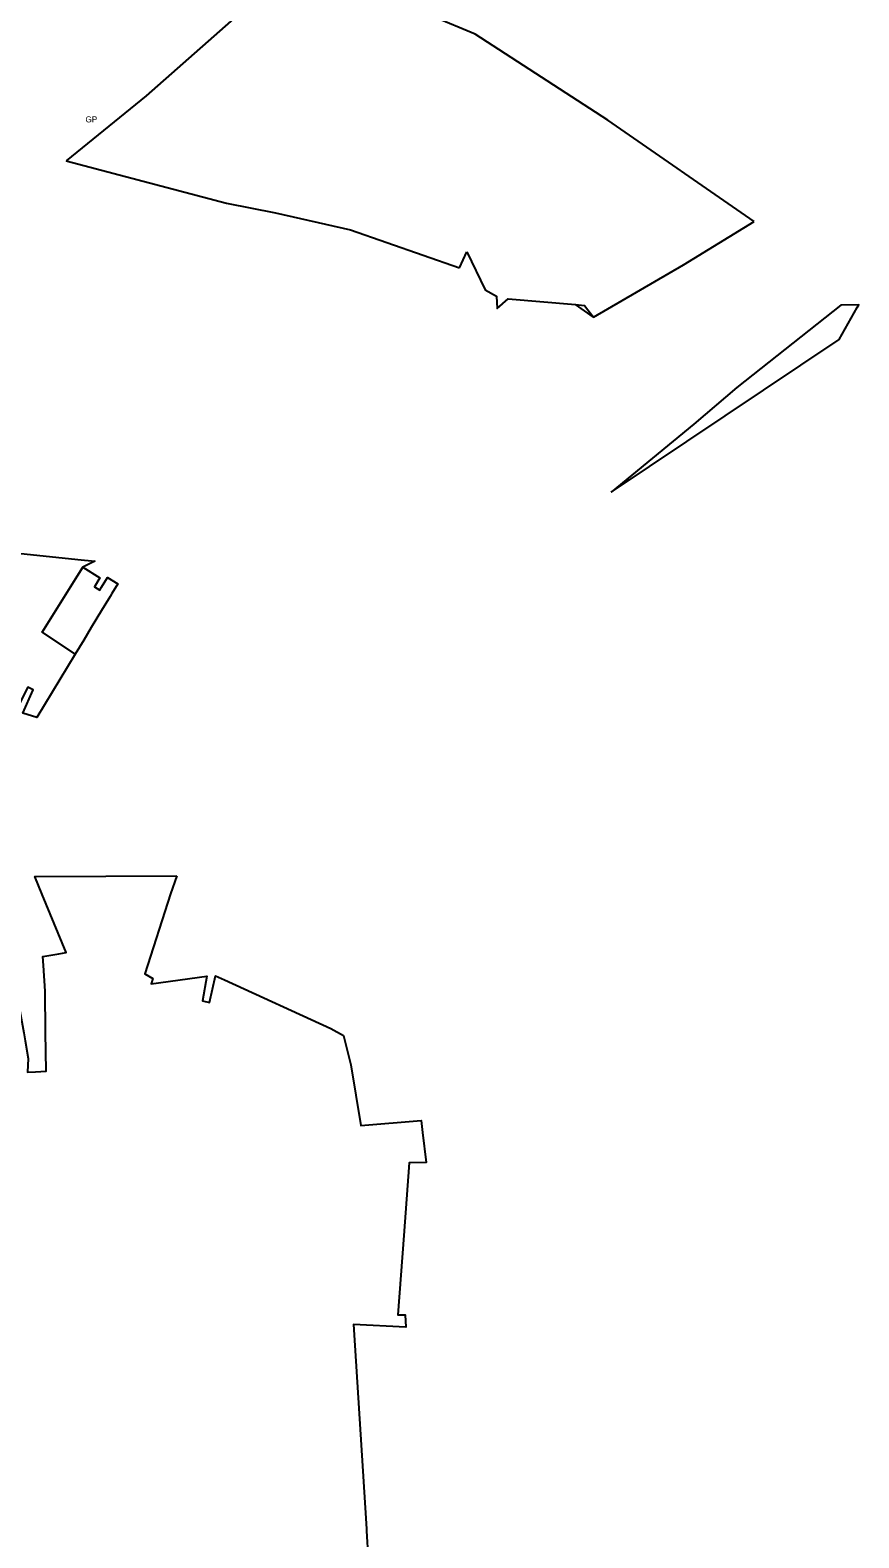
# Model space of a CAD drawing. Extents: x -615719 to -612048, y -1104937 to -1102684.
# Drawn here: x -614082 to -613807.9, y -1103880.3 to -1103382 of the extents above; entities that cross this region are included whole.
import ezdxf

# ---------------------------------------------------------------- set-up
doc = ezdxf.new("R2010")
doc.units = 0
for name, color, linetype in [('GRA_ZV', 7, 'Continuous'), ('OVNI_PRE', 7, 'Continuous'), ('OVNI_SET', 7, 'Continuous'), ('POZN', 7, 'Continuous')]:
    doc.layers.add(name, color=color, linetype=linetype)

msp = doc.modelspace()

# ---------------------------------------------------------------- linework, layer by layer
at = {"layer": 'GRA_ZV'}
for points in [[(-613901.68, -1103472.68), (-613898.69, -1103472.93), (-613895.74, -1103476.88), (-613901.68, -1103472.68)], [(-613889.8, -1103534.71), (-613814.44, -1103484.24), (-613808.46, -1103473.66), (-613807.92, -1103472.71), (-613813.93, -1103472.84), (-613848.23, -1103500.04), (-613862.55, -1103512.21), (-613889.8, -1103534.71)], [(-614086.05, -1103554.8), (-614066.22, -1103556.93), (-614060.57, -1103557.54), (-614064.61, -1103559.48), (-614066.46, -1103562.44), (-614077.99, -1103580.96), (-614067.16, -1103588.26), (-614079.8, -1103609.17), (-614084.44, -1103607.77), (-614081.04, -1103600.03), (-614082.74, -1103599.1), (-614088.16, -1103609.79), (-614091.36, -1103623.82), (-614086.05, -1103554.8)]]:
    msp.add_lwpolyline(points, dxfattribs=at)
at = {"layer": 'OVNI_PRE'}
for points in [[(-614017.12, -1103439.18), (-614000.92, -1103442.32), (-613976.07, -1103447.93), (-613940.05, -1103460.47)], [(-613970.78, -1103877.34), (-613970.75, -1103878.04), (-613970.18, -1103887.33), (-613988.53, -1103889.19)]]:
    msp.add_lwpolyline(points, dxfattribs=at)
at = {"layer": 'OVNI_SET'}
for p, q in [((-614043.63, -1103403.62), (-614070.05, -1103425.19)), ((-613842.51, -1103445.17), (-613891, -1103411.75)), ((-614070.05, -1103425.19), (-614017.12, -1103439.18)), ((-613940.05, -1103460.47), (-613937.63, -1103455.28))]:
    msp.add_line(p, q, dxfattribs=at)
for points in [[(-613934.8, -1103383.27), (-613976.14, -1103365.99), (-613993.27, -1103359.19), (-614043.63, -1103403.62)], [(-613891, -1103411.75), (-613896.93, -1103407.9), (-613934.8, -1103383.27)], [(-613937.63, -1103455.28), (-613931.48, -1103467.77), (-613927.79, -1103469.85), (-613927.6, -1103473.95), (-613923.95, -1103470.8), (-613901.68, -1103472.68), (-613898.69, -1103472.93), (-613895.74, -1103476.88), (-613865.94, -1103459.48), (-613842.51, -1103445.17)], [(-614067.16, -1103588.26), (-614077.99, -1103580.96), (-614066.46, -1103562.44), (-614064.61, -1103559.48)], [(-614064.61, -1103559.48), (-614058.94, -1103563.01), (-614060.77, -1103565.96), (-614059.01, -1103567.04), (-614058.45, -1103566.11), (-614056.47, -1103562.86), (-614053.02, -1103564.96), (-614055, -1103568.23), (-614055.57, -1103569.16)], [(-614055.57, -1103569.16), (-614058.41, -1103573.85), (-614061.82, -1103579.46), (-614064.31, -1103583.57), (-614067.16, -1103588.26)], [(-614091.36, -1103623.82), (-614097.26, -1103647.82), (-614089.82, -1103682.02), (-614084.15, -1103713.42), (-614083.68, -1103716.04), (-614082.62, -1103721.87), (-614082.86, -1103726.44), (-614080.22, -1103726.27), (-614076.72, -1103726.13), (-614076.89, -1103713.24), (-614077.06, -1103699.59), (-614077.59, -1103691.12), (-614077.77, -1103688.14), (-614072.48, -1103687.29), (-614070.05, -1103686.9), (-614078.07, -1103667.71), (-614080.51, -1103661.71), (-614033.49, -1103661.48)], [(-614033.49, -1103661.48), (-614035.6, -1103667.46), (-614044.07, -1103693.85), (-614041.44, -1103695.44), (-614042.01, -1103697.19), (-614023.53, -1103694.72), (-614025, -1103702.86), (-614022.65, -1103703.42), (-614020.73, -1103694.52), (-614017.74, -1103695.92), (-613982.51, -1103712.02), (-613978.35, -1103714.27), (-613975.98, -1103724), (-613972.59, -1103743.99), (-613952.71, -1103742.39), (-613952.25, -1103746.3), (-613951.08, -1103756.22), (-613956.62, -1103756.35), (-613958.46, -1103780.4), (-613960.46, -1103806.57), (-613958, -1103806.6), (-613957.76, -1103810.75), (-613975.02, -1103809.78), (-613970.78, -1103877.34)]]:
    msp.add_lwpolyline(points, dxfattribs=at)

# ---------------------------------------------------------------- texts
at = {"layer": 'POZN'}
msp.add_text('GP', height=2, dxfattribs=at).set_placement((-614063.71, -1103412.46))

doc.saveas('drawing.dxf')
